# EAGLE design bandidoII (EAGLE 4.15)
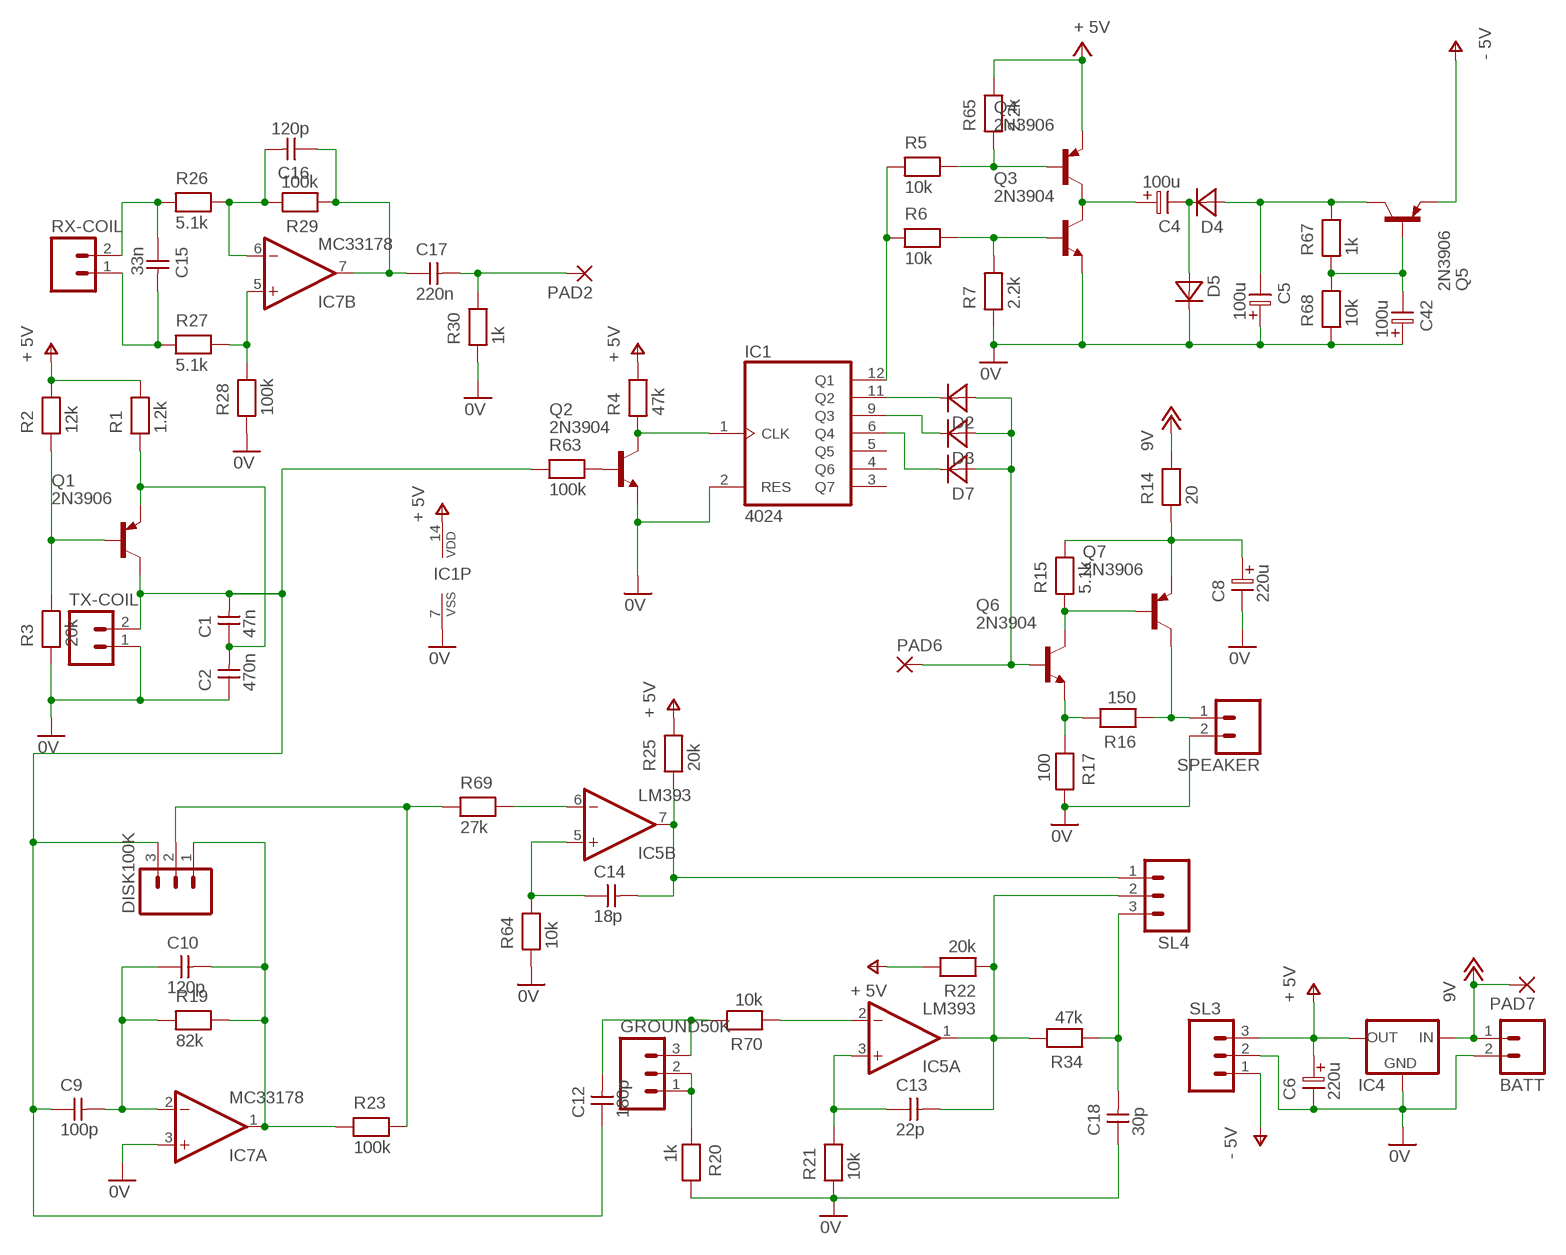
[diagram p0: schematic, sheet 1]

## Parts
BATT  M02  [02P]
C1  47n  CAPNP-5  [C-5]
C2  470n  CAPNP-5  [C-5]
C4  100u  ELC-5  [ES-5]
C5  100u  ELC-5  [ES-5]
C6  220u  ELC-5  [ES-5]
C8  220u  ELC-5  [ES-5]
C9  100p  CAPNP-5  [C-5]
C10  120p  CAPNP-5  [C-5]
C12  180p  CAPNP-5  [C-5]
C13  22p  CAPNP-5  [C-5]
C14  18p  CAPNP-5  [C-5]
C15  33n  CAPNP-5  [C-5]
C16  120p  CAPNP-5  [C-5]
C17  220n  CAPNP-5  [C-5]
C18  30p  CAPNP-5  [C-5]
C42  100u  ELC-5  [ES-5]
D2  DIODE-7,5  [D-7,5]
D3  DIODE-7,5  [D-7,5]
D4  DIODE-7,5  [D-7,5]
D5  DIODE-7,5  [D-7,5]
D7  DIODE-7,5  [D-7,5]
DISK100K  M03  [03P]
GROUND50K  M03  [03P]
IC1  4024  4024N  [DIL14]
IC4  78XXS  [78XXS]
IC5  LM393  LM393N  [DIL08]
IC7  MC33178  LF442N  [DIL08]
PAD2  2,15/1,0  [2,15/1,0]
PAD6  2,15/1,0  [2,15/1,0]
PAD7  2,15/1,0  [2,15/1,0]
Q1  2N3906  [TO92]
Q2  2N3904  [TO92]
Q3  2N3904  [TO92]
Q4  2N3906  [TO92]
Q5  2N3906  [TO92]
Q6  2N3904  [TO92]
Q7  2N3906  [TO92]
R1  1.2k  RESEU-7,5  [R-7,5]
R2  12k  RESEU-7,5  [R-7,5]
R3  20k  RESEU-7,5  [R-7,5]
R4  47k  RESEU-7,5  [R-7,5]
R5  10k  RESEU-7,5  [R-7,5]
R6  10k  RESEU-7,5  [R-7,5]
R7  2.2k  RESEU-7,5  [R-7,5]
R14  20  RESEU-7,5  [R-7,5]
R15  5.1k  RESEU-7,5  [R-7,5]
R16  150  RESEU-7,5  [R-7,5]
R17  100  RESEU-7,5  [R-7,5]
R19  82k  RESEU-7,5  [R-7,5]
R20  1k  RESEU-7,5  [R-7,5]
R21  10k  RESEU-7,5  [R-7,5]
R22  20k  RESEU-7,5  [R-7,5]
R23  100k  RESEU-7,5  [R-7,5]
R25  20k  RESEU-7,5  [R-7,5]
R26  5.1k  RESEU-7,5  [R-7,5]
R27  5.1k  RESEU-7,5  [R-7,5]
R28  100k  RESEU-7,5  [R-7,5]
R29  100k  RESEU-7,5  [R-7,5]
R30  1k  RESEU-7,5  [R-7,5]
R34  47k  RESEU-7,5  [R-7,5]
R63  100k  RESEU-7,5  [R-7,5]
R64  10k  RESEU-7,5  [R-7,5]
R65  2.2k  RESEU-7,5  [R-7,5]
R67  1k  RESEU-7,5  [R-7,5]
R68  10k  RESEU-7,5  [R-7,5]
R69  27k  RESEU-7,5  [R-7,5]
R70  10k  RESEU-7,5  [R-7,5]
RX-COIL  M02  [02P]
SL3  M03  [03P]
SL4  M03  [03P]
SPEAKER  M02  [02P]
TX-COIL  M02  [02P]

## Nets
0V: BATT.2 C2.1 C5.1 C6.2 C8.2 C18.1 C42.1 D5.2(K) IC1.2(RES) IC1.7(VSS) IC4.GND IC7.3(A:+IN) Q2.3(E) Q3.3(E) R3.1 R7.1 R17.2 R20.2 R21.1 R28.1 R30.1 R64.1 R68.1 SL3.2 SPEAKER.2 TX-COIL.1
+12V: BATT.1 IC4.IN PAD7.1(P) R14.2 ; supply symbol labelled 9V
N$1: C15.2 R27.1 RX-COIL.1
N$2: IC5.6(B:-IN) R69.2
N$3: Q1.2(B) R2.1 R3.2
N$4: C1.2 C9.1 C12.1 DISK100K.3 Q1.1(C) R63.1 TX-COIL.2
N$5: C15.1 R26.1 RX-COIL.2
N$6: C16.2 IC7.6(B:-IN) R26.2 R29.2
N$7: C16.1 C17.1 IC7.7(B:OUT) R29.1
N$8: IC7.5(B:+IN) R27.2 R28.2
N$9: C9.2 C10.1 IC7.2(A:-IN) R19.1
N$10: C10.2 DISK100K.1 IC7.1(A:OUT) R19.2 R23.1
N$11: C14.1 IC5.5(B:+IN) R64.2
N$12: DISK100K.2 R23.2 R69.1
N$13: C14.2 IC5.7(B:OUT) R25.1 SL4.1
N$14: C12.2 GROUND50K.3 R70.2
N$15: IC5.2(A:-IN) R70.1
N$16: C13.1 IC5.3(A:+IN) R21.2
N$17: C17.2 PAD2.1(P) R30.2
N$18: C13.2 IC5.1(A:OUT) R22.1 R34.2 SL4.2
N$19: GROUND50K.1 GROUND50K.2 R20.1
N$20: C18.2 R34.1 SL4.3
N$21: Q2.2(B) R63.2
N$22: IC1.1(CLK) Q2.1(C) R4.1
N$23: C42.2 Q5.2(B) R67.1 R68.2
N$24: D2.2(K) IC1.11(Q2)
N$25: D3.2(K) IC1.9(Q3)
N$26: D7.2(K) IC1.6(Q4)
N$27: D2.1(A) D3.1(A) D7.1(A) PAD6.1(P) Q6.2(B)
N$28: IC1.12(Q1) R5.1 R6.1
N$29: Q4.2(B) R5.2 R65.1
N$30: Q3.2(B) R6.2 R7.2
N$31: C4.1 Q3.1(C) Q4.1(C)
N$32: C5.2 D4.1(A) Q5.1(C) R67.2
N$33: Q6.1(C) Q7.2(B) R15.1
N$34: C4.2 D4.2(K) D5.1(A)
N$35: C8.1 Q7.3(E) R14.1 R15.2
N$36: Q6.3(E) R16.2 R17.1
N$37: Q7.1(C) R16.1 SPEAKER.1
N$38: C1.1 C2.2 Q1.3(E) R1.1
V+: C6.1 IC1.14(VDD) IC4.OUT Q4.3(E) R1.2 R2.2 R4.2 R22.2 R25.2 R65.2 SL3.3 ; supply symbol labelled + 5V
V-: Q5.3(E) SL3.1 ; supply symbol labelled - 5V
Unconnected: IC1.3(Q7) IC1.4(Q6) IC1.5(Q5)

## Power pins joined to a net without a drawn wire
V+: IC5.8(P:V+) IC7.8(P:V+)
V-: IC5.4(P:V-) IC7.4(P:V-)

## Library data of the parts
BATT RX-COIL SPEAKER TX-COIL = con-amp-quick:M02: AMP QUICK CONNECTOR
C1 C2 C9 C10 C12-C18 = discrete:CAPNP-5
C4-C6 C8 C42 = discrete:ELC-5
D2-D5 D7 = discrete:DIODE-7,5
DISK100K GROUND50K SL3 SL4 = con-amp-quick:M03: AMP QUICK CONNECTOR
IC1 = 40xx:4024: 7-stage binary/ripple COUNTER
IC4 = v-reg:78XXS: VOLTAGE REGULATOR
IC5 = linear:LM393: COMPARATOR
IC7 = linear:LF442: OP AMP
PAD2 PAD6 PAD7 = wirepad:2,15/1,0: THROUGH-HOLE PAD
Q1 Q4 Q5 Q7 = transistor-pnp:2N3906: PNP Transistor
Q2 Q3 Q6 = transistor-npn:2N3904: NPN Transistor
R1-R7 R14-R17 R19-R23 R25-R30 R34 R63-R65 R67-R70 = discrete:RESEU-7,5

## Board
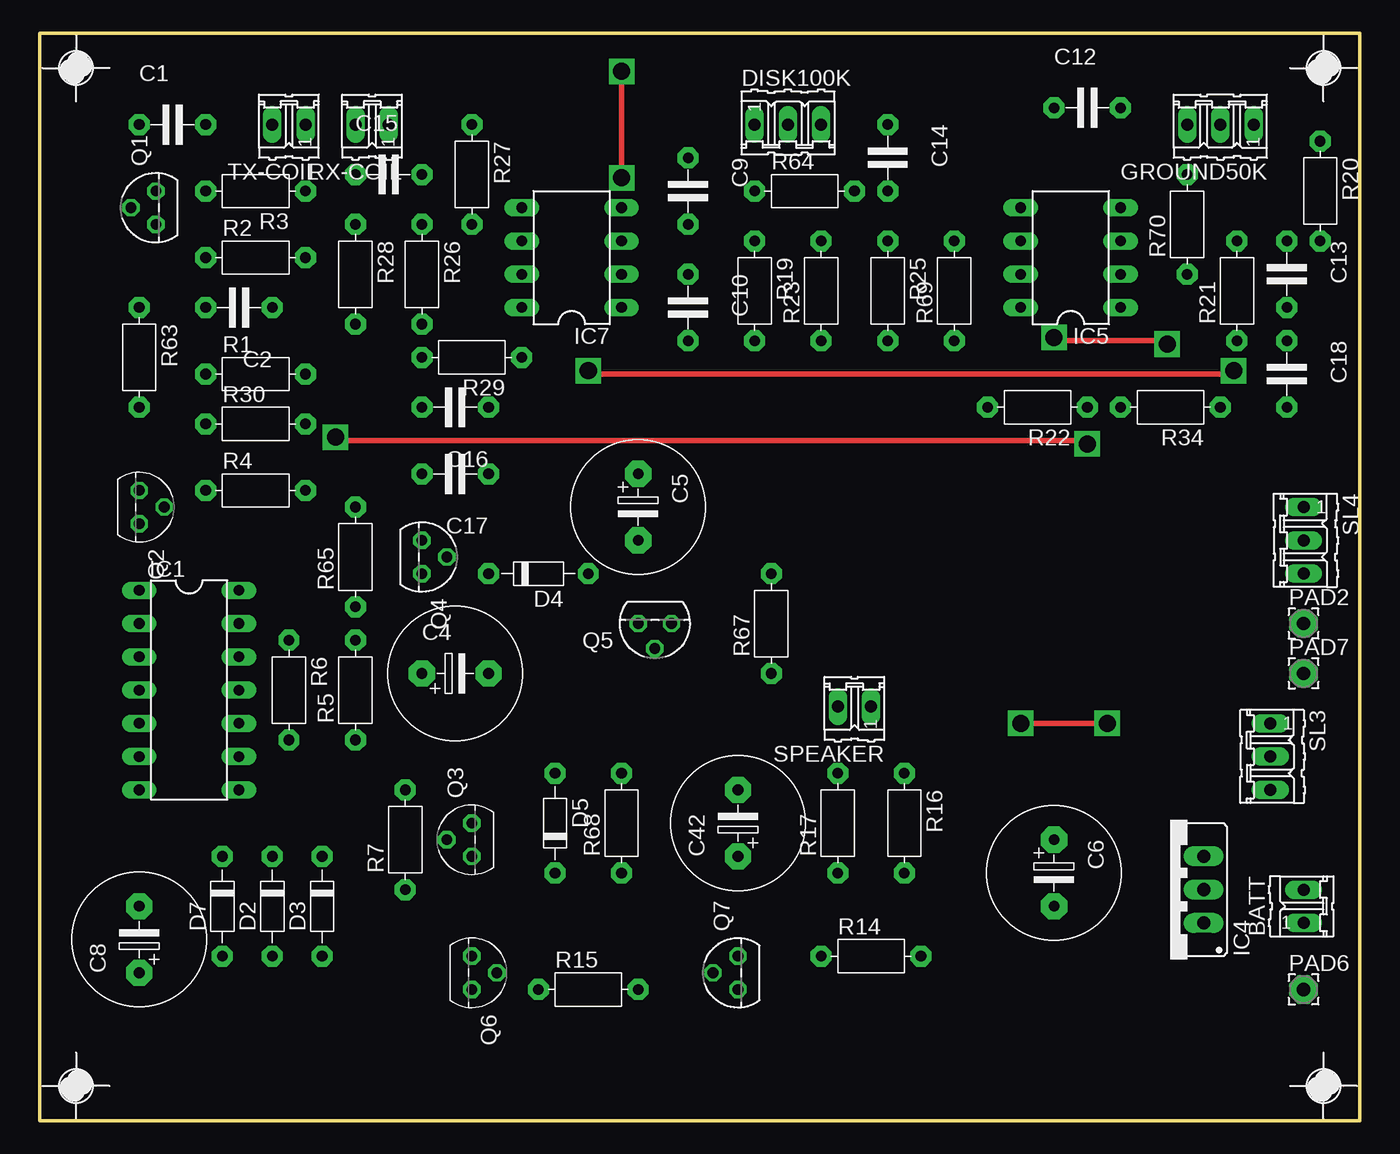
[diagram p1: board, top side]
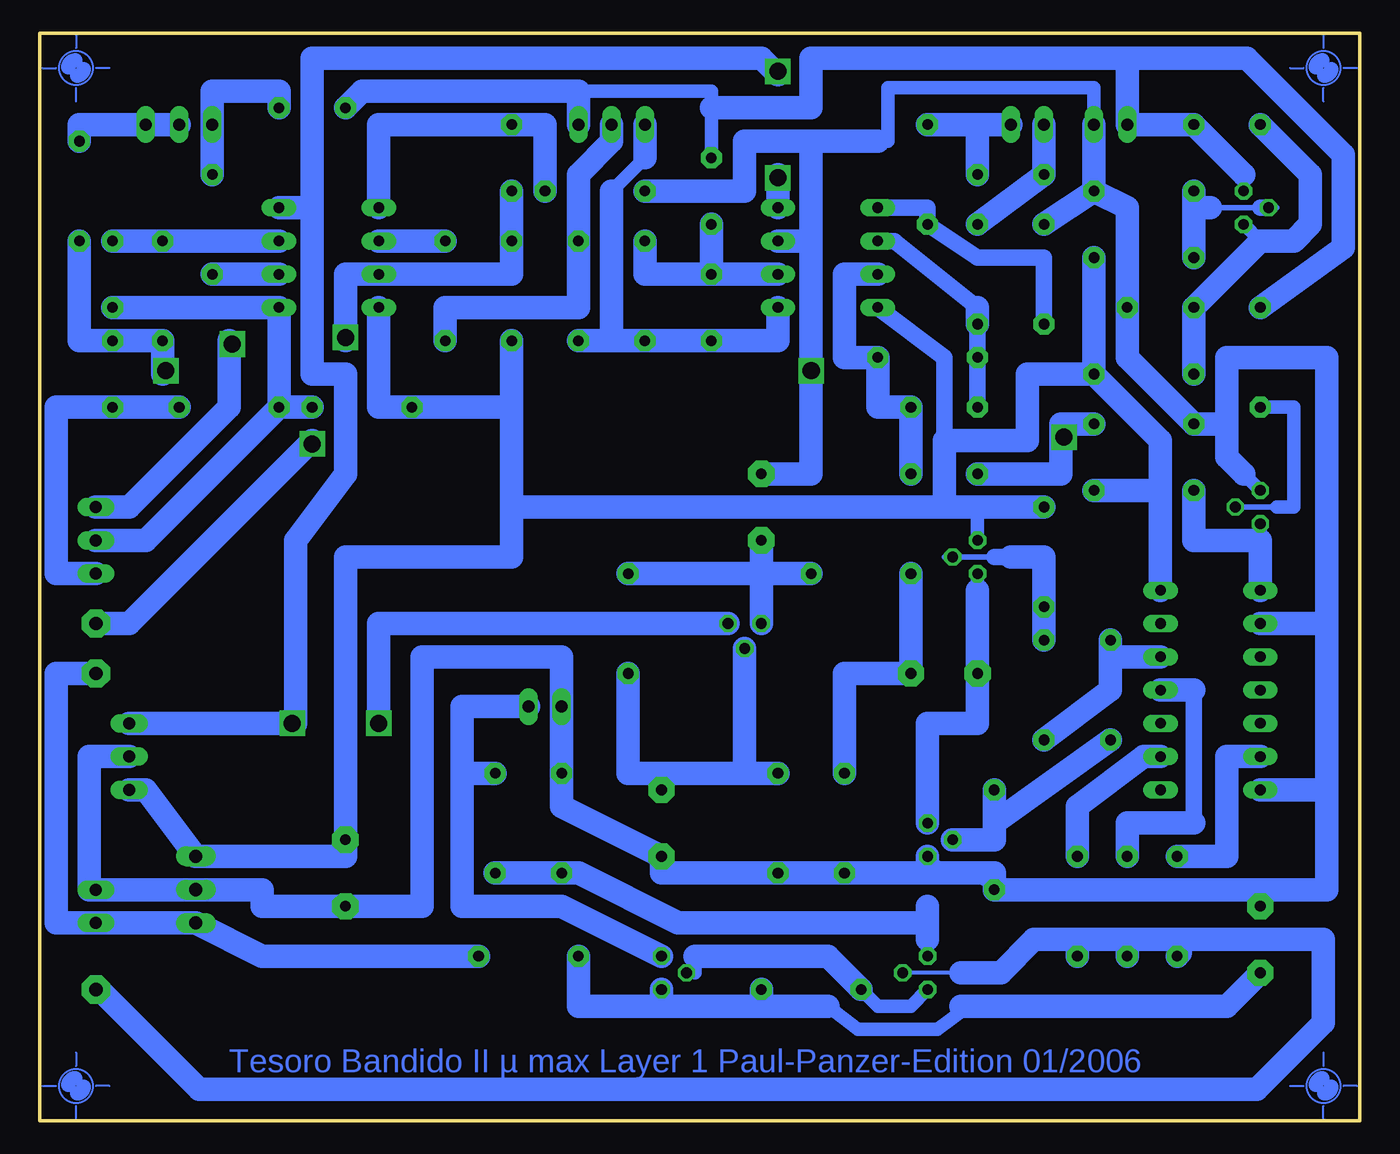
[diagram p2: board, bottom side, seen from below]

Size 100.76 x 83.05 mm. Coordinates in mm from the lower left corner, seen from the top.
Outline: 0,0 100.76,0 100.76,83.05 0,83.05 0,0
Copper layers (1*16): Top 0.035mm / dielectric 1.5mm / Bottom 0.035mm
Design rules "default": minimum track width 10mil, minimum drill 24mil, track to track 8mil, track to pad 8mil, pad to pad 8mil, via to via 8mil, smd to smd 8mil, copper to edge 40mil, drill to drill 8mil, minimum pad ring 10mil, minimum via ring 8mil, stop-mask expansion 4mil, vias tented up to drill 0mil, thermal gap 10mil

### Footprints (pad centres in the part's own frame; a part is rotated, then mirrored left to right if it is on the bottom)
02P = drill 0.914 long: 1 -1.27,0; 2 1.27,0
C-5 = drill 0.813 pad 1.6 octagon: 1 -2.54,0; 2 2.54,0
ES-5 = drill 0.813 pad 2.007 octagon: 1 -2.54,0; 2 2.54,0
D-7,5 = drill 0.813 pad 1.6 octagon: 1 -3.81,0; 2 3.81,0
03P = drill 0.914 long: 1 -2.54,0; 2 0,0; 3 2.54,0
DIL14 = drill 0.813 long: 1 -7.62,-3.81; 2 -5.08,-3.81; 3 -2.54,-3.81; 4 0,-3.81; 5 2.54,-3.81; 6 5.08,-3.81; 7 7.62,-3.81; 8 7.62,3.81; 9 5.08,3.81; 10 2.54,3.81; 11 0,3.81; 12 -2.54,3.81; 13 -5.08,3.81; 14 -7.62,3.81
78XXS = drill 1.016 long: GND 0,-2.54; IN -2.54,-2.54; OUT 2.54,-2.54
DIL08 = drill 0.813 long: 1 -3.81,-3.81; 2 -1.27,-3.81; 3 1.27,-3.81; 4 3.81,-3.81; 5 3.81,3.81; 6 1.27,3.81; 7 -1.27,3.81; 8 -3.81,3.81
2,15/1,0 = drill 1.016 pad 2.159 octagon: 1 0,0
TO92 = drill 0.813 octagon: 1 1.27,0; 2 0,1.905; 3 -1.27,0
R-7,5 = drill 0.813 pad 1.6 octagon: 1 -3.81,0; 2 3.81,0

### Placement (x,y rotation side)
BATT  96.48,16.38 90 top
C1  10.12,76.07 0 top
C2  15.2,62.1 180 top
C4  31.71,34.16 0 top
C5  45.68,46.86 270 top
C6  77.43,18.92 270 top
C8  7.58,13.84 90 top
C9  49.49,70.99 270 top
C10  49.49,62.1 270 top
C12  79.97,77.34 0 top
C13  95.21,64.64 270 top
C14  64.73,73.53 270 top
C15  26.63,72.26 0 top
C16  31.71,54.48 180 top
C17  31.71,49.4 180 top
C18  95.21,57.02 270 top
C42  53.3,22.73 90 top
D2  17.74,16.38 90 top
D3  21.55,16.38 90 top
D4  38.06,41.78 180 top
D5  39.33,22.73 270 top
D7  13.93,16.38 90 top
DISK100K  57.11,76.07 0 top
GROUND50K  90.13,76.07 180 top
IC1  11.39,32.89 270 top
IC4  86.32,17.65 90 top
IC5  78.7,65.91 90 top
IC7  40.6,65.91 90 top
PAD2  96.48,37.97 0 top
PAD6  96.48,10.03 0 top
PAD7  96.48,34.16 0 top
Q1  8.85,69.72 90 top
Q2  7.58,46.86 270 top
Q3  32.98,21.46 90 top
Q4  29.17,43.05 270 top
Q5  46.95,37.97 180 top
Q6  32.98,11.3 270 top
Q7  53.3,11.3 90 top
R1  16.47,57.02 0 top
R2  16.47,65.91 0 top
R3  16.47,70.99 180 top
R4  16.47,48.13 0 top
R5  24.09,32.89 90 top
R6  19.01,32.89 270 top
R7  27.9,21.46 90 top
R14  63.46,12.57 0 top
R15  41.87,10.03 0 top
R16  66,22.73 270 top
R17  60.92,22.73 90 top
R19  54.57,63.37 270 top
R20  97.75,70.99 270 top
R21  91.4,63.37 90 top
R22  76.16,54.48 180 top
R23  59.65,63.37 90 top
R25  64.73,63.37 270 top
R26  29.17,64.64 270 top
R27  32.98,72.26 270 top
R28  24.09,64.64 270 top
R29  32.98,58.29 180 top
R30  16.47,53.21 0 top
R34  86.32,54.48 180 top
R63  7.58,58.29 270 top
R64  58.38,70.99 0 top
R65  24.09,43.05 90 top
R67  55.84,37.97 90 top
R68  44.41,22.73 90 top
R69  69.81,63.37 90 top
R70  87.59,68.45 90 top
RX-COIL  25.36,76.07 180 top
SL3  93.94,27.81 270 top
SL4  96.48,44.32 270 top
SPEAKER  62.19,31.62 180 top
TX-COIL  19.01,76.07 180 top
U$1  [PASS-ROUND]  98.01,80.39 0 top
U$2  [PASS-ROUND]  2.76,80.39 0 top
U$3  [PASS-ROUND]  2.76,2.66 0 top
U$4  [PASS-ROUND]  98.01,2.66 0 top

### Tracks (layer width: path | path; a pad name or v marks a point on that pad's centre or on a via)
0V  (via drill 0.61, 0.61 pad 0.61, 1.3)
  Top 0.406: v41.87,57.02 v91.4,57.02
  Bottom 0.254: R7.1 Q3.3
  Bottom 0.61: 7.58,17.65 C8.2 | IC4.GND 87.59,17.65
  Bottom 1.016: 8.85,49.4 Q2.3 | 36.79,74.8 36.03,74.8 36.03,78.86 20.28,78.86 TX-COIL.1
  Bottom 1.778: SL3.2 96.99,27.81 96.99,17.65 BATT.2 IC4.GND 83.78,17.65 83.78,16.38 C6.2 71.59,16.38 71.59,35.43 60.92,35.43 SPEAKER.2 R17.2 60.92,24 C42.1 53.3,18.92 R68.1 D5.2 32.98,18.92 | v91.4,57.02 R21.1 C18.1 97.75,59.56 R20.2 | Q3.3 32.98,18.92 | 32.98,18.92 27.9,18.92 R7.1 7.58,17.65 2.5,17.65 2.5,25.27 | 2.5,25.27 2.5,37.97 | 2.5,25.27 IC1.7 | 2.5,37.97 IC1.2 | 2.5,37.97 2.5,58.29 10.12,58.29 10.12,53.21 | 10.12,53.21 R30.1 17.74,58.29 C2.1 17.74,69.72 R3.1 | 10.12,53.21 10.12,50.67 8.85,49.4 | 41.87,74.8 41.87,67.18 | 41.87,67.18 v41.87,57.27 v41.87,57.02 41.87,49.4 C5.1 | 41.87,67.18 IC7.3 | 41.87,74.8 46.95,74.8 46.95,70.99 R64.1 | R3.1 TX-COIL.1 | R3.1 R28.1 | 36.79,74.8 41.87,74.8
+12V
  Bottom 0.61: BATT.1 97.75,15.11
  Bottom 1.016: PAD7.1 96.23,34.16
  Bottom 1.778: R14.2 83.78,12.57 IC4.IN BATT.1 99.53,15.11 99.53,34.16 PAD7.1
N$1
  Bottom 1.778: 29.17,76.07 RX-COIL.1 | 29.17,76.07 R27.1 | C15.2 29.17,76.07
N$2
  Bottom 1.778: R69.2 IC5.6
N$3
  Bottom 0.406: Q1.2 6.31,69.72 | 7.58,69.72 11.39,69.72
  Bottom 1.27: Q1.2 7.58,69.72
  Bottom 1.778: 12.66,69.72 R2.1 | 12.66,69.72 R3.2 | 11.39,69.72 12.66,69.72
N$4
  Bottom 0.254: DISK100K.3 59.65,77.34
  Bottom 0.61: Q1.1 8.85,72.26
  Bottom 1.016: 59.65,78.61 49.49,78.61 49.49,77.34 C9.1
  Bottom 1.778: 8.85,72.26 C1.2 TX-COIL.2 17.74,81.15 | C12.1 76.16,78.61 59.65,78.61 DISK100K.3 | 49.49,77.34 41.87,77.34 41.87,81.15 17.74,81.15 | 17.74,81.15 8.6,81.15 1.23,73.78 1.23,66.67 R63.1
N$5
  Bottom 1.778: RX-COIL.2 C15.1 R26.1
N$6
  Bottom 1.27: IC7.6 35.52,67.18 29.17,62.1 | R26.2 R29.2 C16.2
  Bottom 1.778: R26.2 29.17,62.1
N$7
  Bottom 1.778: C17.1 C16.1 36.79,54.48 R29.1 39.33,58.29 39.33,64.64 IC7.7
N$8
  Bottom 1.27: R28.2 24.09,65.91 29.17,65.91 R27.2 32.98,69.72 IC7.5
N$9
  Bottom 1.778: IC7.2 C10.1 | C10.1 C9.2 | C10.1 54.57,64.64 R19.1
N$10
  Bottom 1.016: 57.11,70.99 54.57,73.53
  Bottom 1.778: IC7.1 44.41,59.56 C10.2 R19.2 57.11,59.56 | 57.11,59.56 R23.1 | 57.11,59.56 57.11,70.99 | 54.57,73.53 DISK100K.1
N$11
  Bottom 1.778: R64.2 62.19,76.07 C14.1 74.89,76.07 IC5.5
N$12
  Bottom 1.778: R69.1 69.81,62.1 59.65,62.1 R23.2 59.65,72.26 57.11,74.8 DISK100K.2
N$13  (via drill 0.61, 0.61 pad 0.61, 1.3)
  Top 0.406: v77.43,59.56 v86.32,59.56
  Bottom 1.778: v86.32,59.56 86.32,54.48 93.94,46.86 SL4.1 | v77.43,59.56 v77.43,59.81 77.43,64.64 IC5.7 64.73,64.64 R25.1 C14.2
N$14
  Bottom 1.778: C12.2 82.51,78.61 87.59,78.61 GROUND50K.3 R70.2
N$15
  Bottom 1.778: IC5.2 R70.1
N$16
  Bottom 1.778: C13.1 R21.2 IC5.3
N$17  (via drill 0.61 pad 0.81, 1.3)
  Top 0.406: v22.82,51.94 v79.97,51.94
  Bottom 0.254: v79.97,51.94 v79.97,51.68
  Bottom 1.778: PAD2.1 93.94,37.97 v79.97,51.94 | C17.2 22.82,49.4 v22.82,51.94 22.82,53.21 R30.2
N$18
  Bottom 1.778: R22.1 R34.2 | C13.2 IC5.1 R34.2 | SL4.2 92.67,44.32 R34.2
N$19
  Bottom 1.778: GROUND50K.2 GROUND50K.1 97.75,76.07 R20.1
N$20
  Bottom 1.778: 94.96,54.48 R34.1 | SL4.3 99.53,41.78 99.53,54.48 94.96,54.48 | 94.96,54.48 C18.2
N$21
  Bottom 0.254: 8.85,46.86 Q2.2
  Bottom 0.406: 6.31,46.86 8.85,46.86
  Bottom 1.016: R63.2 5.04,54.48 5.04,46.86 6.31,46.86
N$22
  Bottom 1.016: 7.58,44.32 Q2.1
  Bottom 1.778: IC1.1 7.58,44.32 12.66,44.32 R4.1
N$23
  Bottom 1.778: 46.95,26.54 53.3,26.54 | 53.3,26.54 C42.2 | R68.2 46.95,26.54 | 46.95,26.54 46.95,32.89 | 46.95,32.89 46.95,35.43 | R67.1 55.84,26.54 53.3,26.54 | 46.95,32.89 Q5.2
N$24
  Bottom 1.27: 12.66,22.73 12.66,32.89
  Bottom 1.778: D2.2 17.74,22.73 12.66,22.73 | 12.66,32.89 IC1.11
N$25
  Bottom 1.778: IC1.9 16.47,27.81 21.55,24 D3.2
N$26
  Bottom 1.778: D7.2 10.12,20.19 10.12,27.81 IC1.6
N$27
  Bottom 0.305: 30.44,11.3 Q6.2
  Bottom 1.778: PAD6.1 96.23,10.03 88.61,2.41 7.84,2.41 2.76,7.49 2.76,13.84 13.68,13.84 | D7.1 13.68,12.82 13.68,13.84 | 13.68,13.84 17.74,13.84 | 17.74,13.84 D2.1 | 17.74,13.84 21.55,13.84 | 21.55,13.84 D3.1 | 21.55,13.84 24.85,13.84 27.39,11.3 30.44,11.3
N$28
  Bottom 1.778: IC1.12 19.01,35.43 | 19.01,35.43 R6.1 | 19.01,35.43 19.01,32.89 R5.1
N$29
  Bottom 0.254: 27.9,43.05 Q4.2
  Bottom 0.406: 27.9,43.05 31.71,43.05
  Bottom 1.27: 26.63,43.05 27.9,43.05
  Bottom 1.778: R5.2 R65.1 24.09,43.05 26.63,43.05
N$30
  Bottom 1.778: Q3.2 27.9,21.46 27.9,22.73 | 27.9,22.73 R7.2 | R6.2 27.9,22.73
N$31
  Bottom 1.016: 29.17,40.51 Q4.1
  Bottom 1.778: Q3.1 32.98,30.35 29.17,30.35 C4.1 29.17,40.51
N$32
  Bottom 1.778: 45.68,41.78 R67.2 | 45.68,41.78 C5.2 | 45.68,41.78 D4.1 | Q5.1 45.68,41.78
N$33
  Bottom 0.254: 50.76,11.3 Q7.2
  Bottom 1.016: Q6.1 34.25,8.76 36.79,8.76 R15.1 | 50.76,12.57 50.76,11.3
  Bottom 1.778: 50.76,12.57 40.6,12.57 R15.1
N$34
  Bottom 0.254: C4.2 D4.2
  Bottom 1.778: D4.2 C4.2 39.33,34.16 D5.1
N$35
  Bottom 1.016: 40.6,8.76 38.32,6.98 32.22,6.98 30.19,8.5 30.19,8.76 30.19,9.01
  Bottom 1.778: 45.68,8.76 R15.2 | 40.6,8.76 45.68,8.76 | 30.44,8.76 30.19,8.76 10.12,8.76 C8.1 | R14.1 59.65,8.76 53.3,8.76 | 45.68,8.76 53.3,8.76 | 53.3,8.76 Q7.3
N$36
  Bottom 1.016: Q6.3 32.98,13.84
  Bottom 1.778: R16.2 R17.1 59.65,18.92 52.03,15.11 32.98,15.11 | 32.98,13.84 32.98,15.11 | 32.98,15.11 32.98,16.38
N$37
  Bottom 1.778: Q7.1 60.92,16.38 68.54,16.38 68.54,26.54 | 68.54,26.54 68.54,31.62 SPEAKER.1 | 68.54,26.54 R16.1
N$38
  Bottom 1.016: 7.58,67.18 Q1.3
  Bottom 1.778: R1.1 C2.2 7.58,67.18 5.04,67.18 3.77,68.45 3.77,72.26 C1.1
N$39  (via drill 1.3)
  other vias: 44.41,80.13
N$40  (via drill 1.3)
  other vias: 86.07,59.3
N$41  (via drill 1.3)
  other vias: 91.15,57.27
N$42  (via drill 1.3)
  other vias: 74.89,30.35
N$43  (via drill 1.3)
  other vias: 22.57,52.19
V+
  Bottom 1.016: 29.17,46.86 Q4.3
  Bottom 1.27: 31.71,51.94 31.71,58.29 IC7.8
  Bottom 1.778: SL3.3 92.67,25.27 IC4.OUT 77.43,20.19 C6.1 77.43,43.05 64.73,43.05 64.73,46.86 | 64.73,46.86 64.73,54.48 | 64.73,54.48 R25.2 | 64.73,54.48 R22.2 74.89,54.48 IC5.8 | IC1.14 15.2,48.13 | 15.2,48.13 15.2,51.94 R1.2 | 15.2,48.13 R4.2 | 31.71,46.86 64.73,46.86 | 31.71,46.86 29.17,46.86 R65.2 | 31.71,46.86 31.71,51.94 25.36,51.94 25.36,57.02 R1.2 | R1.2 R2.2
V-  (via drill 0.61, 0.61 pad 0.81, 1.3)
  Top 0.406: v44.41,79.88 v44.41,72.26 | v74.89,30.35 v81.24,30.35
  Bottom 1.778: v74.89,30.35 74.89,37.97 Q5.3 | SL3.1 v81.5,30.35 v81.24,30.35 81.24,44.32 77.43,49.4 77.43,57.02 79.97,57.02 79.97,69.72 | 79.97,69.72 IC5.4 | IC7.4 v44.41,72 v44.41,72.26 | 79.97,69.72 79.97,81.15 45.68,81.15 v44.41,79.88

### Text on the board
Bottom: Tesoro Bandido II µ max Layer 1 Paul-Panzer-Edition 01/2006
